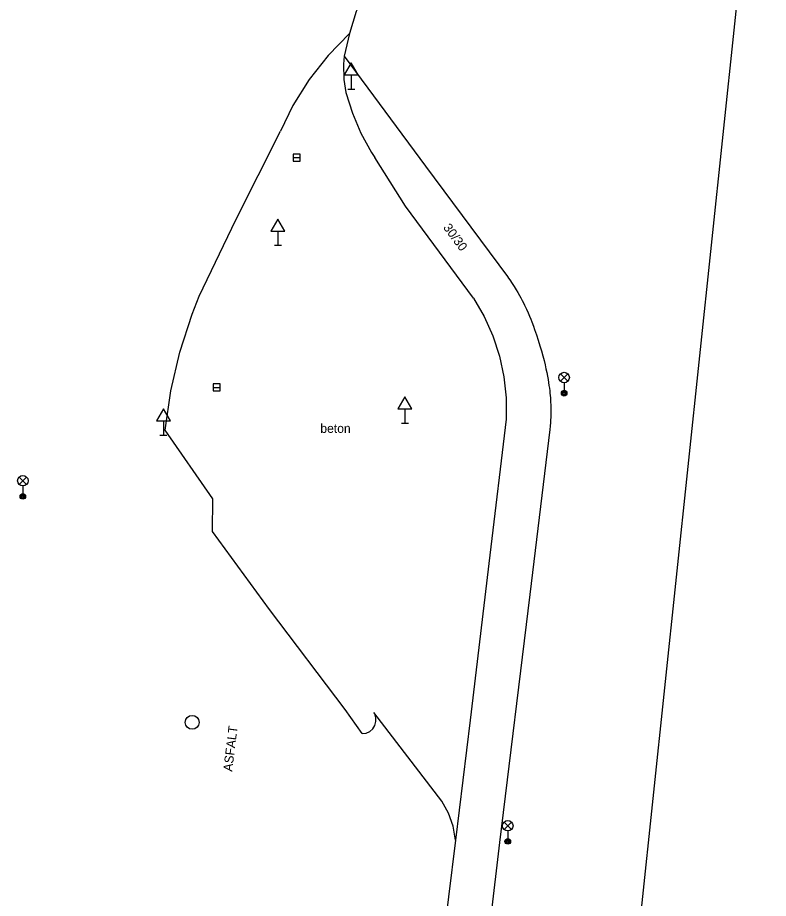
# Model space of a CAD drawing. Extents: x -541281 to -539153, y -1183881 to -1182141.
# Drawn here: x -539771 to -539717.2, y -1183288.6 to -1183225.4 of the extents above; entities that cross this region are included whole.
import ezdxf

# ---------------------------------------------------------------- set-up
doc = ezdxf.new("R2010")
doc.units = 0
for name, color, linetype in [('Vrstva 10', 7, 'Continuous'), ('Vrstva 11', 7, 'Continuous'), ('Vrstva 27', 7, 'Continuous'), ('Vrstva 33', 7, 'Continuous'), ('Vrstva 34', 7, 'Continuous'), ('Vrstva 40', 7, 'Continuous'), ('Vrstva 7', 7, 'Continuous')]:
    doc.layers.add(name, color=color, linetype=linetype)

msp = doc.modelspace()

# ---------------------------------------------------------------- linework, layer by layer
at = {"layer": 'Vrstva 10'}
for p, q in [((-539755.32, -1183239.87), (-539752.12, -1183233.52)), ((-539743.15, -1183238.9), (-539745.36, -1183235.4)), ((-539738.28, -1183245.51), (-539743.15, -1183238.9)), ((-539757.96, -1183245.36), (-539755.32, -1183239.87)), ((-539735.95, -1183254.19), (-539737.12, -1183263.94)), ((-539756.97, -1183259.89), (-539760.38, -1183254.98)), ((-539756.99, -1183262.24), (-539756.97, -1183259.89)), ((-539752.9, -1183267.83), (-539756.99, -1183262.24)), ((-539737.12, -1183263.94), (-539738.53, -1183275.77)), ((-539747.48, -1183275.02), (-539752.9, -1183267.83)), ((-539746.26, -1183276.74), (-539747.48, -1183275.02)), ((-539740.56, -1183281.58), (-539745.42, -1183275.22)), ((-539738.53, -1183275.77), (-539739.57, -1183284.37)), ((-539739.57, -1183284.37), (-539740.084, -1183288.449)), ((-539740.084, -1183288.449), (-539740.89, -1183295.02))]:
    msp.add_line(p, q, dxfattribs=at)
for points in [[(-539742.67, -1183218.994), (-539743.067, -1183219.51), (-539743.413, -1183219.969), (-539743.713, -1183220.374), (-539743.976, -1183220.734), (-539744.204, -1183221.051), (-539744.404, -1183221.331), (-539744.752, -1183221.827), (-539745.012, -1183222.204), (-539745.207, -1183222.489), (-539745.499, -1183222.922), (-539745.79, -1183223.36), (-539745.883, -1183223.502), (-539746.057, -1183223.779), (-539746.213, -1183224.041), (-539746.353, -1183224.287), (-539746.478, -1183224.52), (-539746.591, -1183224.738), (-539746.691, -1183224.944), (-539747.18, -1183226.52)], [(-539747.18, -1183226.52), (-539748.716, -1183228.089), (-539750.071, -1183229.815), (-539751.23, -1183231.68), (-539752.12, -1183233.52)], [(-539747.18, -1183226.52), (-539747.557, -1183228.131), (-539747.607, -1183228.705), (-539747.582, -1183229.821), (-539747.44, -1183230.74)], [(-539747.44, -1183230.74), (-539746.971, -1183232.235), (-539746.353, -1183233.674), (-539745.591, -1183235.042), (-539745.36, -1183235.4)], [(-539760.38, -1183254.98), (-539759.975, -1183252.152), (-539759.335, -1183249.368), (-539758.463, -1183246.647), (-539757.96, -1183245.36)], [(-539738.28, -1183245.51), (-539737.517, -1183246.822), (-539736.896, -1183248.208), (-539736.425, -1183249.65), (-539736.107, -1183251.135), (-539735.948, -1183252.644), (-539735.949, -1183254.162), (-539735.95, -1183254.19)], [(-539746.26, -1183276.74), (-539745.981, -1183276.695), (-539745.726, -1183276.575), (-539745.514, -1183276.388), (-539745.363, -1183276.149), (-539745.285, -1183275.878), (-539745.286, -1183275.595), (-539745.365, -1183275.324), (-539745.42, -1183275.22)], [(-539739.57, -1183284.37), (-539739.753, -1183283.384), (-539740.09, -1183282.439), (-539740.56, -1183281.58)]]:
    msp.add_lwpolyline(points, dxfattribs=at)
at = {"layer": 'Vrstva 11'}
for p, q in [((-539747.557, -1183228.131), (-539741.72, -1183236.02)), ((-539741.72, -1183236.02), (-539735.86, -1183243.94)), ((-539732.82, -1183254.92), (-539734.255, -1183266.77)), ((-539734.255, -1183266.77), (-539736.416, -1183284.545)), ((-539736.416, -1183284.545), (-539737.495, -1183293.432))]:
    msp.add_line(p, q, dxfattribs=at)
for points in [[(-539735.86, -1183243.94), (-539735.767, -1183244.068), (-539735.678, -1183244.193), (-539735.511, -1183244.438), (-539735.361, -1183244.671), (-539735.225, -1183244.892), (-539735.102, -1183245.101), (-539734.99, -1183245.3), (-539734.888, -1183245.488), (-539734.795, -1183245.665), (-539734.71, -1183245.833), (-539734.632, -1183245.992), (-539734.491, -1183246.293), (-539734.373, -1183246.56), (-539734.272, -1183246.796), (-539734.187, -1183247.004), (-539734.115, -1183247.187), (-539733.992, -1183247.512), (-539733.903, -1183247.758), (-539733.774, -1183248.132), (-539733.65, -1183248.51), (-539733.526, -1183248.91), (-539733.416, -1183249.286), (-539733.318, -1183249.637), (-539733.233, -1183249.967), (-539733.158, -1183250.277), (-539733.092, -1183250.567), (-539733.035, -1183250.839), (-539732.986, -1183251.094), (-539732.943, -1183251.333), (-539732.907, -1183251.557), (-539732.876, -1183251.767), (-539732.849, -1183251.964), (-539732.827, -1183252.148), (-539732.808, -1183252.322), (-539732.779, -1183252.646), (-539732.76, -1183252.93), (-539732.749, -1183253.179)], [(-539732.749, -1183253.179), (-539732.743, -1183253.397), (-539732.742, -1183253.587), (-539732.743, -1183253.754), (-539732.751, -1183254.045), (-539732.761, -1183254.264), (-539732.772, -1183254.428), (-539732.793, -1183254.674), (-539732.82, -1183254.92)]]:
    msp.add_lwpolyline(points, dxfattribs=at)
at = {"layer": 'Vrstva 27'}
for p, q in [((-539751.21, -1183235.42), (-539750.71, -1183235.42)), ((-539756.94, -1183251.9), (-539756.44, -1183251.9))]:
    msp.add_line(p, q, dxfattribs=at)
for points in [[(-539751.21, -1183235.67), (-539750.71, -1183235.67), (-539750.71, -1183235.17), (-539751.21, -1183235.17)], [(-539756.94, -1183252.15), (-539756.44, -1183252.15), (-539756.44, -1183251.65), (-539756.94, -1183251.65)]]:
    msp.add_lwpolyline(points, close=True, dxfattribs=at)
msp.add_circle((-539758.45, -1183275.93), 0.5, dxfattribs=at)
at = {"layer": 'Vrstva 33'}
for p, q in [((-539732.055, -1183251.46), (-539731.525, -1183250.93)), ((-539732.055, -1183250.93), (-539731.525, -1183251.46)), ((-539731.79, -1183251.57), (-539731.79, -1183252.32)), ((-539770.855, -1183258.86), (-539770.325, -1183258.33)), ((-539770.855, -1183258.33), (-539770.325, -1183258.86)), ((-539770.59, -1183258.97), (-539770.59, -1183259.72)), ((-539736.095, -1183283.61), (-539735.565, -1183283.08)), ((-539736.095, -1183283.08), (-539735.565, -1183283.61)), ((-539735.83, -1183283.72), (-539735.83, -1183284.47))]:
    msp.add_line(p, q, dxfattribs=at)
for centre, radius in [((-539731.79, -1183251.195), 0.375), ((-539731.79, -1183252.32), 0.2), ((-539731.79, -1183252.32), 0.145), ((-539731.79, -1183252.32), 0.0876), ((-539770.59, -1183258.595), 0.375), ((-539770.59, -1183259.72), 0.2), ((-539770.59, -1183259.72), 0.145), ((-539770.59, -1183259.72), 0.0876), ((-539735.83, -1183283.345), 0.375), ((-539735.83, -1183284.47), 0.2), ((-539735.83, -1183284.47), 0.145), ((-539735.83, -1183284.47), 0.0876)]:
    msp.add_circle(centre, radius, dxfattribs=at)
at = {"layer": 'Vrstva 34'}
for p, q in [((-539747.05, -1183229.482), (-539747.05, -1183230.5)), ((-539747.3, -1183230.5), (-539746.8, -1183230.5)), ((-539752.31, -1183240.692), (-539752.31, -1183241.71)), ((-539752.56, -1183241.71), (-539752.06, -1183241.71)), ((-539743.2, -1183253.442), (-539743.2, -1183254.46)), ((-539760.51, -1183254.312), (-539760.51, -1183255.33)), ((-539743.45, -1183254.46), (-539742.95, -1183254.46)), ((-539760.76, -1183255.33), (-539760.26, -1183255.33))]:
    msp.add_line(p, q, dxfattribs=at)
for points in [[(-539747.55, -1183229.482), (-539746.55, -1183229.482), (-539747.05, -1183228.616)], [(-539752.81, -1183240.692), (-539751.81, -1183240.692), (-539752.31, -1183239.826)], [(-539743.7, -1183253.442), (-539742.7, -1183253.442), (-539743.2, -1183252.576)], [(-539761.01, -1183254.312), (-539760.01, -1183254.312), (-539760.51, -1183253.446)]]:
    msp.add_lwpolyline(points, close=True, dxfattribs=at)
at = {"layer": 'Vrstva 7'}
msp.add_lwpolyline([(-539735.64, -1183375.86), (-539735, -1183369.96), (-539726.24, -1183289.32), (-539718.71, -1183217.87), (-539717.15, -1183202.86)], dxfattribs=at)

# ---------------------------------------------------------------- texts
at = {"layer": 'Vrstva 40'}
for s, rotation, p in [('30/30', 306.49769, (-539740.492, -1183240.441)), ('ASFALT', 83.07518, (-539755.588, -1183279.484))]:
    msp.add_text(s, height=0.65, rotation=rotation, dxfattribs=at).set_placement(p)
msp.add_text('beton', height=0.65, dxfattribs=at).set_placement((-539749.266, -1183255.164))

doc.saveas('drawing.dxf')
